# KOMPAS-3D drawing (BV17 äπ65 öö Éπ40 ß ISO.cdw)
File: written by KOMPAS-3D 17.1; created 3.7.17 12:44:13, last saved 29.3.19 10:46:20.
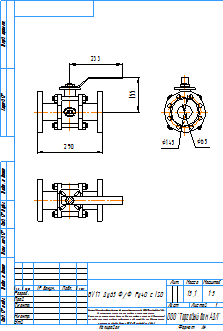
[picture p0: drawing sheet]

Sheet 1: A4, portrait

Title block, sheet 1: name: BV17 Ду65 Ф/Ф Ру40 с ISO; material: Сталь 20  ГОСТ 1050-88; mass: 15,1; sheets: 1; sheet format: A4; stored path: C:\Users\kka\KOMPAS_Work\!Trash\СС02 СС03 ФФ Смотровые стекла\СС01.cdw

Views: Спереди 1, Проекционный вид 2, Проекционный вид 3
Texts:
  Klimkovich
  ADL
  Рама для чертежей
  Лит-Масса-Масштаб
  Материал-Предприятие
  Масштаб
  Изм.
  Лист
  № докум.
  Подп.
  Дата
  Лит.
  Разраб.
  Пров.
  Т.контр.
  Листов
  Внимание! Данный продукт является объектом авторского права ООО «Торговый Дом АДЛ».
  Запрещается изменение, копирование, распространение
  (в том числе путем копирования на другие сайты и ресурсы в Интернете)
  или любое иное использование информации и объектов без предварительного
  согласия правообладателя (ООО «Торговый Дом АДЛ»).
  Н.контр.
  Утв.
  ООО "Торговый дом АДЛ"
  Изменение
  Номер документа
  Подпись
  Обозначение документа
  Наименование изделия
  Масса изделия по ГОСТ 2.109-73
  Порядковый номер листа
  Общее количество листов в документе
  Характер работы, выполненной лицом, подписавшим документ
  Наименование или индекс предприятия, выпускающего документ
  Инв. № подл.
  Подп. и дата
  Взам. инв. №
  Инв. № дубл.
  Инвентарный номер подлинника по ГОСТ 2.501-68
  Подпись принявшего подлинник в отдел технической документации
  Инвентарный номер подлинника, взамен которого выпущен данный подлинник
  Инвентарный номер дубликата по ГОСТ 2.502-68
  Подпись принявшего дубликат в отдел технической документации
  Справ. №
  Перв. примен.
  Обозначение документа, взамен или на основании которого выпущен данный документ
  Обозначение документа, в котором впервые записан данный документ
  Подпись лица, копировавшего чертеж
  Обозначение формата листа
  !Рама для чертежа
Dimensions and other numbers on the sheet: 233; 290; 155; 145; 65; 1:5; 1; 15,1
